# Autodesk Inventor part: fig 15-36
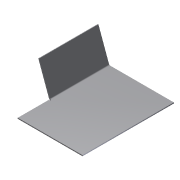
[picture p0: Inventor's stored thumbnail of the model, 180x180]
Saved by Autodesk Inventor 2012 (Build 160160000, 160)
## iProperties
Created: 2005-03
Part Number: fig 15-36
Document SubType Name: Sheet Metal
Designer: CADCIM
Manufacturer: Standard
Standards Organization: Custom
Density: 1 g/cm^3
Sheet Metal Rule: Default
Material: Default
Author: CADCIM
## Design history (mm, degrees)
node "Face1"
  sketch "Sketch1"
    geometry: L1 (31.393, 35.714)-(-17.775, 35.714); L2 (-17.775, 35.714)-(-17.775, 5.625); L3 (-17.775, 5.625)-(-1.5, 5.625); L4 (-1.5, 5.625)-(-1.5, -10.705); L5 (-1.5, -10.705)-(31.393, -10.705); L6 (31.393, -10.705)-(31.393, 35.714)
    constraints: 12 end point, 4 parallel, 1 horizontal, 1 perpendicular
sketch "Sketch3"
  geometry: L1 (16.275, -30.089)-(16.275, 0); L2 (16.275, -46.42)-(16.275, -30.089) reference; L3 (16.275, -30.089)-(0, -30.089) reference; L4 (0, 0)-(49.168, 0) reference
  constraints: 3 point on line, 2 end point, 1 vertical
feature "Fold1" sketch "Sketch3" dims "d1" = 0.5 (= BendReliefWidth), "d2" = 0.25 (= BendReliefDepth), "d3" = 1 (= MinimumRemnant), "d4" = 0.5 (= BendRadius), "d5" = 70 deg, "d6" = 0.5 (= BendRadius), "SeamGap" = 0.01, "Thickness" = 0.5
body "Solid1"
face "Plate1" dims "Thickness" = 0.5
other parameters: "BendRadius" = 0.5 (= Thickness), "BendReliefWidth" = 0.5 (= Thickness), "BendReliefDepth" = 0.25 (= 0.5 x Thickness), "CornerReliefSize" = 2 (= 4 x Thickness), "MinimumRemnant" = 1 (= 2 x Thickness), "TransitionRadius" = 0.5 (= BendRadius), "d0" = 0.5 (= BendRadius), "JacobiRadiusSize" = 0.5 (= Thickness), "GapSize" = 0.5 (= Thickness)
